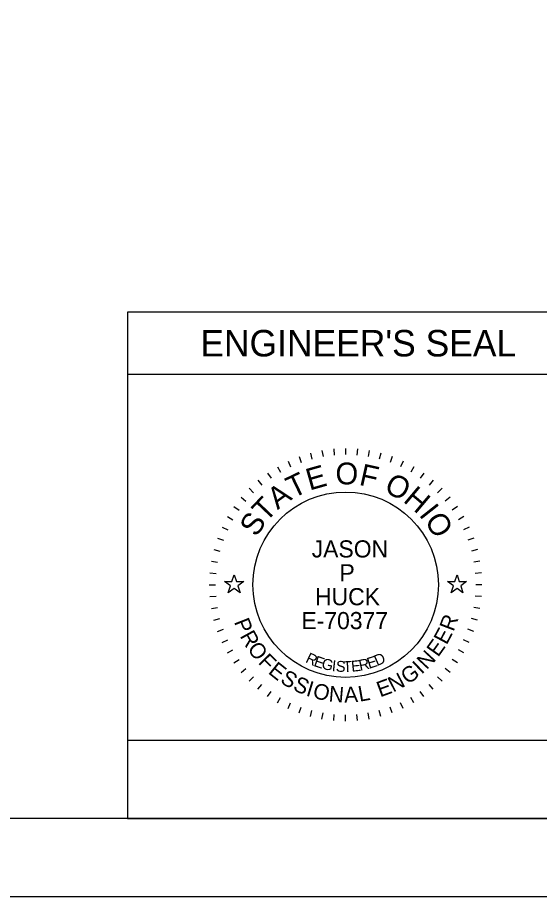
# Model space of a CAD drawing. Extents: x -2.1 to 31.9, y 6.3 to 28.3.
# Drawn here: x 4.58 to 7.93, y 6.34 to 11.98 of the extents above; entities that cross this region are included whole.
import ezdxf

# ---------------------------------------------------------------- set-up
doc = ezdxf.new("R2010")
doc.units = 0
for name, color, linetype in [('Default', 7, 'Continuous'), ('SH_Border', 7, 'Continuous'), ('SH_Cut_Line', 7, 'Continuous'), ('SH_Data', 7, 'Continuous')]:
    doc.layers.add(name, color=color, linetype=linetype)

msp = doc.modelspace()

# ---------------------------------------------------------------- linework, layer by layer
at = {"layer": 'Default'}
for points in [[(5.9081, 8.3639), (5.9549, 8.3639), (5.9694, 8.4085), (5.9839, 8.3639), (6.0308, 8.3639), (5.9929, 8.3363), (6.0074, 8.2917), (5.9694, 8.3193), (5.9315, 8.2917), (5.946, 8.3363)], [(7.3381, 8.3639), (7.3849, 8.3639), (7.3994, 8.4085), (7.4139, 8.3639), (7.4608, 8.3639), (7.4229, 8.3363), (7.4374, 8.2917), (7.3994, 8.3193), (7.3615, 8.2917), (7.376, 8.3363)]]:
    msp.add_lwpolyline(points, close=True, dxfattribs=at)
at = {"layer": 'SH_Border'}
msp.add_lwpolyline([(-0.5656, 27.844), (31.4344, 27.844), (31.4344, 6.844), (-0.5656, 6.844)], close=True, dxfattribs=at)
at = {"layer": 'SH_Cut_Line'}
msp.add_lwpolyline([(-2.0656, 6.344), (31.9344, 6.344), (31.9344, 28.344), (-2.0656, 28.344)], close=True, dxfattribs=at)
at = {"layer": 'SH_Data'}
for p, q in [((8.0844, 10.094), (5.2844, 10.094)), ((5.2844, 10.094), (5.2844, 6.844)), ((8.0844, 9.694), (5.2844, 9.694)), ((6.5325, 9.2057), (6.5394, 9.1663)), ((6.6082, 9.2156), (6.6117, 9.1758)), ((6.6844, 9.219), (6.6844, 9.179)), ((6.7607, 9.2156), (6.7572, 9.1758)), ((6.8364, 9.2057), (6.8294, 9.1663)), ((6.3146, 9.137), (6.3316, 9.1007)), ((6.3852, 9.1662), (6.3989, 9.1286)), ((6.458, 9.1891), (6.4683, 9.1505)), ((6.9109, 9.1891), (6.9006, 9.1505)), ((6.9837, 9.1662), (6.97, 9.1286)), ((7.0542, 9.137), (7.0373, 9.1007)), ((6.2469, 9.1017), (6.2669, 9.0671)), ((7.1219, 9.1017), (7.1019, 9.0671)), ((6.1826, 9.0607), (6.2055, 9.028)), ((7.1863, 9.0607), (7.1634, 9.028)), ((6.122, 9.0142), (6.1477, 8.9836)), ((7.2469, 9.0142), (7.2212, 8.9836)), ((6.0657, 8.9627), (6.094, 8.9344)), ((7.3032, 8.9627), (7.2749, 8.9344)), ((6.0142, 8.9064), (6.0448, 8.8807)), ((7.3547, 8.9064), (7.3241, 8.8807)), ((5.9677, 8.8458), (6.0004, 8.8229)), ((7.4012, 8.8458), (7.3684, 8.8229)), ((5.9267, 8.7815), (5.9613, 8.7615)), ((7.4422, 8.7815), (7.4076, 8.7615)), ((5.8914, 8.7138), (5.9277, 8.6968)), ((7.4775, 8.7138), (7.4412, 8.6968)), ((5.8622, 8.6432), (5.8998, 8.6295)), ((7.5067, 8.6432), (7.4691, 8.6295)), ((5.8393, 8.5704), (5.8779, 8.5601)), ((7.5296, 8.5704), (7.491, 8.5601)), ((5.8227, 8.4959), (5.8621, 8.489)), ((7.5461, 8.4959), (7.5068, 8.489)), ((5.8128, 8.4202), (5.8526, 8.4167)), ((7.5561, 8.4202), (7.5163, 8.4167)), ((5.8094, 8.344), (5.8494, 8.344)), ((7.5594, 8.344), (7.5194, 8.344)), ((5.8128, 8.2677), (5.8526, 8.2712)), ((7.5561, 8.2677), (7.5163, 8.2712)), ((5.8227, 8.192), (5.8621, 8.199)), ((7.5461, 8.192), (7.5068, 8.199)), ((5.8393, 8.1175), (5.8779, 8.1278)), ((7.5296, 8.1175), (7.491, 8.1278)), ((5.8622, 8.0447), (5.8998, 8.0584)), ((7.5067, 8.0447), (7.4691, 8.0584)), ((5.8914, 7.9742), (5.9277, 7.9911)), ((7.4775, 7.9742), (7.4412, 7.9911)), ((5.9267, 7.9065), (5.9613, 7.9265)), ((7.4422, 7.9065), (7.4076, 7.9265)), ((5.9677, 7.8421), (6.0004, 7.865)), ((7.4012, 7.8421), (7.3684, 7.865)), ((6.0142, 7.7815), (6.0448, 7.8072)), ((7.3547, 7.7815), (7.3241, 7.8072)), ((6.0657, 7.7252), (6.094, 7.7535)), ((7.3032, 7.7252), (7.2749, 7.7535)), ((6.122, 7.6737), (6.1477, 7.7043)), ((7.2469, 7.6737), (7.2212, 7.7043)), ((6.1826, 7.6272), (6.2055, 7.66)), ((6.2469, 7.5862), (6.2669, 7.6208)), ((7.1219, 7.5862), (7.1019, 7.6208)), ((7.1863, 7.6272), (7.1634, 7.66)), ((6.3146, 7.5509), (6.3316, 7.5872)), ((6.3852, 7.5217), (6.3989, 7.5593)), ((6.9837, 7.5217), (6.97, 7.5593)), ((7.0542, 7.5509), (7.0373, 7.5872)), ((6.458, 7.4988), (6.4683, 7.5374)), ((6.5325, 7.4823), (6.5394, 7.5216)), ((6.6082, 7.4723), (6.6117, 7.5121)), ((6.6844, 7.469), (6.6844, 7.509)), ((6.7607, 7.4723), (6.7572, 7.5121)), ((6.8364, 7.4823), (6.8294, 7.5216)), ((6.9109, 7.4988), (6.9006, 7.5374)), ((8.0844, 6.844), (5.2844, 6.844))]:
    msp.add_line(p, q, dxfattribs=at)
msp.add_lwpolyline([(8.0844, 6.844), (8.0844, 7.344), (5.2844, 7.344), (5.2844, 6.844)], close=True, dxfattribs=at)
msp.add_circle((6.6844, 8.344), 0.595, dxfattribs=at)

# ---------------------------------------------------------------- texts
for s, height, p in [("ENGINEER'S SEAL", 0.17, (5.752, 9.809)), ('JASON', 0.11, (6.4666, 8.5189)), ('P', 0.11, (6.6449, 8.3656)), ('HUCK', 0.11, (6.4879, 8.2123)), ('E-70377', 0.11, (6.4004, 8.059))]:
    msp.add_text(s, height=height, dxfattribs=at).set_placement(p)
for s, height, rotation, p in [('E', 0.14, 15.7571, (6.4529, 8.9478)), ('O', 0.14, 359.7812, (6.6192, 8.9882)), ('F', 0.14, 347.4362, (6.7655, 8.9857)), ('T', 0.14, 25.7167, (6.3461, 8.8958)), ('O', 0.14, 332.2586, (6.9243, 8.9455)), ('A', 0.14, 36.4747, (6.2478, 8.8221)), ('H', 0.14, 319.9136, (7.0476, 8.8801)), ('T', 0.14, 46.4344, (6.1727, 8.7404)), ('I', 0.14, 308.367, (7.1509, 8.7923)), ('S', 0.14, 57.1924, (6.1125, 8.6454)), ('O', 0.14, 303.1491, (7.1866, 8.7528)), ('P', 0.1, 291.494, (5.9667, 8.106)), ('R', 0.1, 69.2322, (7.3764, 8.0393)), ('E', 0.1, 61.9951, (7.3321, 7.9538)), ('R', 0.1, 298.7311, (6.0034, 8.0157)), ('O', 0.1, 306.4666, (6.0499, 7.9323)), ('E', 0.1, 54.758, (7.2778, 7.8753)), ('F', 0.1, 314.7068, (6.1187, 7.8422)), ('R', 0.07, 334.487, (6.4219, 7.849)), ('D', 0.07, 23.3052, (6.8854, 7.821)), ('N', 0.1, 47.0224, (7.2046, 7.7947)), ('E', 0.1, 321.4393, (6.1822, 7.7788)), ('E', 0.07, 341.04, (6.4751, 7.824)), ('G', 0.07, 347.4752, (6.5259, 7.8058)), ('I', 0.07, 353.7858, (6.5935, 7.7908)), ('S', 0.07, 356.8926, (6.6202, 7.7868)), ('T', 0.07, 3.0061, (6.6701, 7.7826)), ('E', 0.07, 6.0117, (6.7234, 7.7852)), ('R', 0.07, 11.9184, (6.7769, 7.7913)), ('E', 0.07, 17.6836, (6.8342, 7.8041)), ('I', 0.1, 43.287, (7.1713, 7.7653)), ('S', 0.1, 328.6764, (6.2588, 7.7192)), ('G', 0.1, 35.0469, (7.0825, 7.701)), ('S', 0.1, 335.9134, (6.3409, 7.6705)), ('E', 0.1, 20.0742, (6.9057, 7.621)), ('N', 0.1, 27.3113, (6.9889, 7.6515)), ('I', 0.1, 343.1505, (6.4251, 7.6336)), ('O', 0.1, 346.8859, (6.4683, 7.6191)), ('N', 0.1, 355.1261, (6.5733, 7.5957)), ('A', 0.1, 2.8617, (6.6767, 7.5876)), ('L', 0.1, 10.0987, (6.7738, 7.593))]:
    msp.add_text(s, height=height, rotation=rotation, dxfattribs=at).set_placement(p)

doc.saveas('drawing.dxf')
